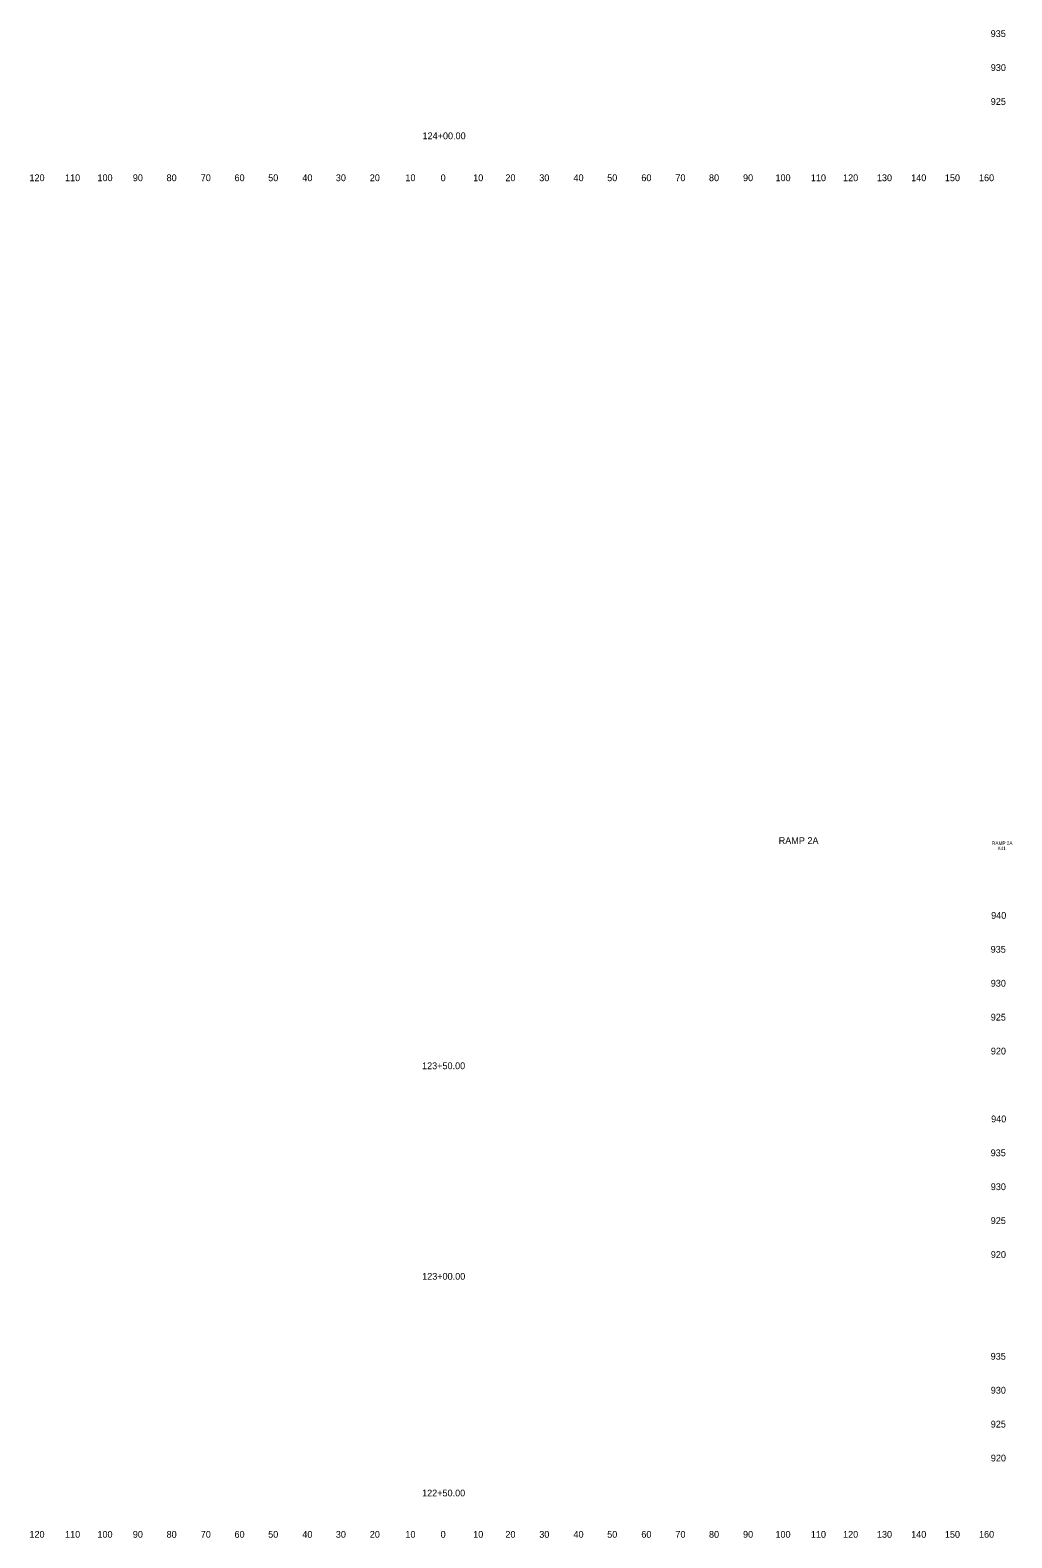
# Model space of a CAD drawing. Extents: x 4994 to 7388, y 4997 to 8804.
# Drawn here: x 7098.2 to 7387.8, y 4997.5 to 5442 of the extents above; entities that cross this region are included whole.
import ezdxf

# ---------------------------------------------------------------- set-up
doc = ezdxf.new("R2010")
doc.units = 0
for name, color, linetype in [('RD_SHT_ID', 7, 'Continuous'), ('RD_XS_TX_Offset', 7, 'Continuous'), ('RD_XS_TX_Station', 7, 'Continuous')]:
    doc.layers.add(name, color=color, linetype=linetype)

msp = doc.modelspace()

# ---------------------------------------------------------------- texts
at = {"layer": 'RD_SHT_ID'}
for s, height, p in [('RAMP 2A', 2, (7319.02, 5202.06)), ('RAMP 2A', 1, (7381.93, 5201.8)), ('X41', 1, (7383.57, 5200.3))]:
    msp.add_text(s, height=height, dxfattribs=at).set_placement(p)
at = {"layer": 'RD_XS_TX_Offset'}
for s, p in [('935', (7381.55, 5440)), ('930', (7381.58, 5430)), ('925', (7381.57, 5420)), ('120', (7098.01, 5397.5)), ('110', (7108.51, 5397.5)), ('100', (7118.07, 5397.5)), ('90', (7128.5, 5397.5)), ('80', (7138.46, 5397.5)), ('70', (7148.54, 5397.5)), ('60', (7158.5, 5397.5)), ('50', (7168.43, 5397.5)), ('40', (7178.5, 5397.5)), ('30', (7188.39, 5397.5)), ('20', (7198.4, 5397.5)), ('10', (7208.91, 5397.5)), ('0', (7219.3, 5397.5)), ('0', (7219.3, 5397.5)), ('10', (7228.91, 5397.5)), ('20', (7238.4, 5397.5)), ('30', (7248.39, 5397.5)), ('40', (7258.5, 5397.5)), ('50', (7268.43, 5397.5)), ('60', (7278.5, 5397.5)), ('70', (7288.54, 5397.5)), ('80', (7298.46, 5397.5)), ('90', (7308.5, 5397.5)), ('100', (7318.07, 5397.5)), ('110', (7328.51, 5397.5)), ('120', (7338.01, 5397.5)), ('130', (7347.99, 5397.5)), ('140', (7358.1, 5397.5)), ('150', (7368.04, 5397.5)), ('160', (7378.1, 5397.5)), ('940', (7381.69, 5180)), ('935', (7381.55, 5170)), ('930', (7381.58, 5160)), ('925', (7381.57, 5150)), ('920', (7381.6, 5140)), ('940', (7381.69, 5120)), ('935', (7381.55, 5110)), ('930', (7381.58, 5100)), ('925', (7381.57, 5090)), ('920', (7381.6, 5080)), ('935', (7381.55, 5050)), ('930', (7381.58, 5040)), ('925', (7381.57, 5030)), ('920', (7381.6, 5020)), ('120', (7098.01, 4997.5)), ('110', (7108.51, 4997.5)), ('100', (7118.07, 4997.5)), ('90', (7128.5, 4997.5)), ('80', (7138.46, 4997.5)), ('70', (7148.54, 4997.5)), ('60', (7158.5, 4997.5)), ('50', (7168.43, 4997.5)), ('40', (7178.5, 4997.5)), ('30', (7188.39, 4997.5)), ('20', (7198.4, 4997.5)), ('10', (7208.91, 4997.5)), ('0', (7219.3, 4997.5)), ('0', (7219.3, 4997.5)), ('10', (7228.91, 4997.5)), ('20', (7238.4, 4997.5)), ('30', (7248.39, 4997.5)), ('40', (7258.5, 4997.5)), ('50', (7268.43, 4997.5)), ('60', (7278.5, 4997.5)), ('70', (7288.54, 4997.5)), ('80', (7298.46, 4997.5)), ('90', (7308.5, 4997.5)), ('100', (7318.07, 4997.5)), ('110', (7328.51, 4997.5)), ('120', (7338.01, 4997.5)), ('130', (7347.99, 4997.5)), ('140', (7358.1, 4997.5)), ('150', (7368.04, 4997.5)), ('160', (7378.1, 4997.5))]:
    msp.add_text(s, height=2, dxfattribs=at).set_placement(p)
at = {"layer": 'RD_XS_TX_Station'}
for s, p in [('124+00.00', (7213.96, 5409.87)), ('123+50.00', (7213.82, 5135.66)), ('123+00.00', (7213.85, 5073.58)), ('122+50.00', (7213.83, 5009.69))]:
    msp.add_text(s, height=2, dxfattribs=at).set_placement(p)

doc.saveas('drawing.dxf')
